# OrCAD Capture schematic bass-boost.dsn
size A
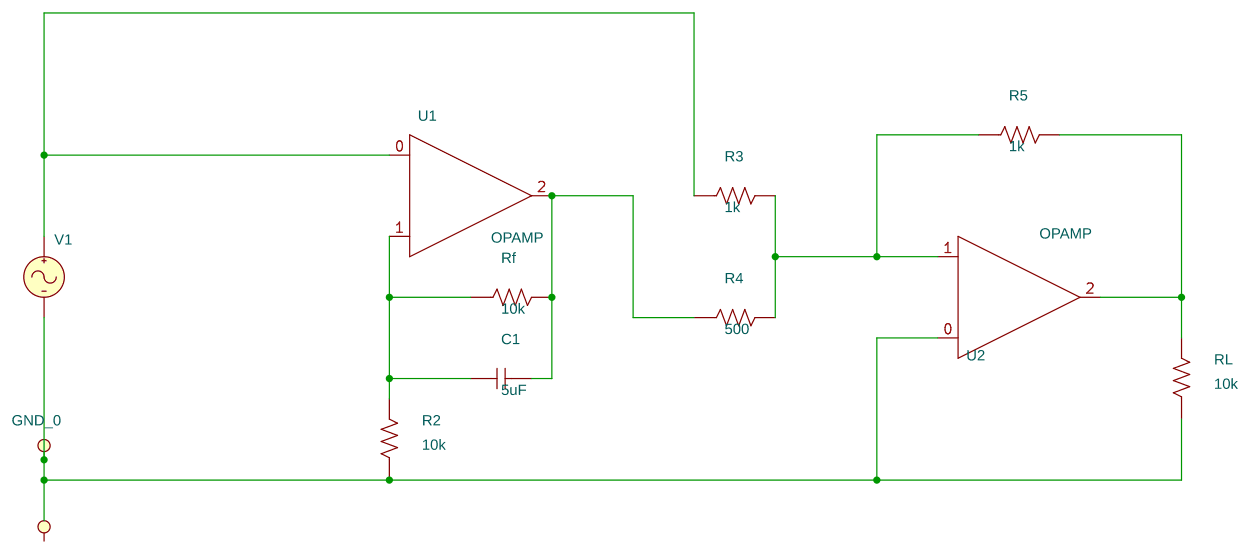
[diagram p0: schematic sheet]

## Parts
C1  5uF  [cap196]
R2  10k  [AXRC05]
R3  1k  [AXRC05]
R4  500  [AXRC05]
R5  1k  [AXRC05]
Rf  10k  [AXRC05]
RL  10k  [AXRC05]
U1  OPAMP
U2  OPAMP
V1  VAC

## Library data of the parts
C1 = C
R2-R5 Rf RL = R
U1 U2 = OPAMP
V1 = VAC

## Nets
0: R2.1 RL.1 U2.0(+) V1.2(-)
N15614: R3.1 U1.0(+) V1.1(+)
N15676: C1.2 R4.1 Rf.2 U1.2(OUT)
N15688: C1.1 R2.2 Rf.1 U1.1(-)
N16090: R3.2 R4.2 R5.1 U2.1(-)
N16147: R5.2 RL.2 U2.2(OUT)
